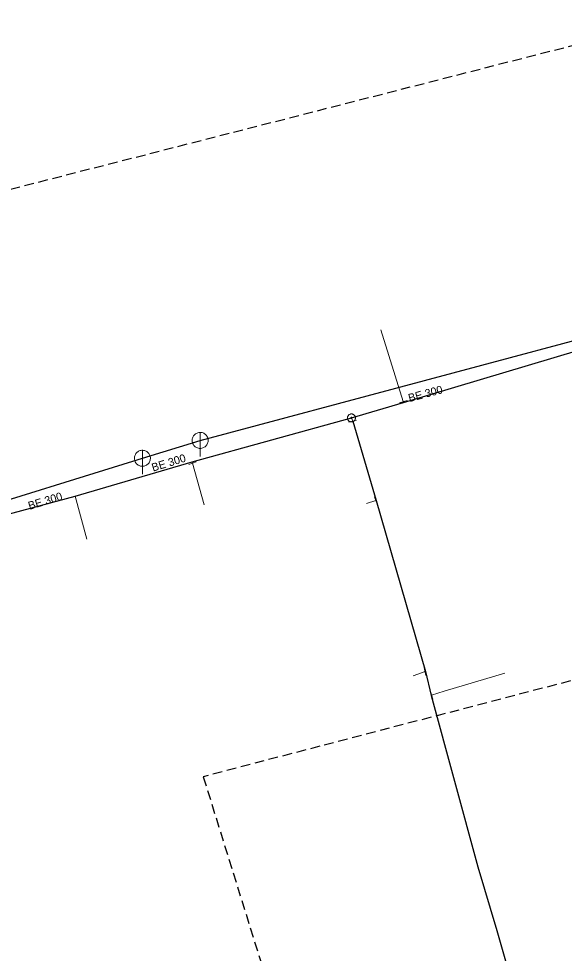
# Model space of a CAD drawing. Extents: x -690254 to -689100, y -975264 to -974703.
# Drawn here: x -689647.4 to -689579.1, y -974992.3 to -974875.5 of the extents above; entities that cross this region are included whole.
import ezdxf

# ---------------------------------------------------------------- set-up
doc = ezdxf.new("R2010")
doc.units = 0
doc.header["$LTSCALE"] = 0.4
doc.linetypes.add('MEDIUM_DASHED', pattern=[4.5, 3, -1.5])
for name, color, linetype, lineweight in [('1', 7, 'Continuous', 13), ('13', 7, 'Continuous', 13), ('14', 7, 'Continuous', 13), ('17', 7, 'Continuous', 25), ('22', 7, 'Continuous', 13), ('34', 7, 'Continuous', 13), ('47', 7, 'Continuous', 13), ('63', 7, 'MEDIUM_DASHED', 25)]:
    doc.layers.add(name, color=color, linetype=linetype, lineweight=lineweight)

msp = doc.modelspace()

# ---------------------------------------------------------------- linework, layer by layer
at = {"layer": '13'}
for p, q in [((-689599.281, -974923.341), (-689602.067, -974914.367)), ((-689625.632, -974931.027), (-689624.183, -974936.227)), ((-689640.32, -974935.166), (-689638.85, -974940.521)), ((-689602.706, -974935.695), (-689603.87, -974936.09)), ((-689596.556, -974957.073), (-689598.039, -974957.59))]:
    msp.add_line(p, q, dxfattribs=at)
msp.add_lwpolyline([(-689595.726, -974960.045), (-689594.17, -974959.52), (-689586.561, -974957.285)], dxfattribs=at)
at = {"layer": '14'}
for p, q in [((-689599.249, -974923.443), (-689599.281, -974923.341)), ((-689605.589, -974925.779), (-689605.756, -974925.377)), ((-689625.688, -974930.875), (-689625.632, -974931.027)), ((-689602.66, -974935.68), (-689602.706, -974935.695)), ((-689596.5, -974957.059), (-689596.556, -974957.073)), ((-689595.726, -974960.045), (-689595.8, -974960.07))]:
    msp.add_line(p, q, dxfattribs=at)
at = {"layer": '14', "lineweight": 25}
for points in [[(-689624.679, -974928.186), (-689568.576, -974913.204), (-689527.509, -974901.581), (-689488.181, -974889.533)], [(-689655.57, -974937.75), (-689631.897, -974930.421), (-689624.679, -974928.186)]]:
    msp.add_lwpolyline(points, dxfattribs=at)
at = {"layer": '17'}
for points in [[(-689605.756, -974925.377), (-689599.249, -974923.443), (-689573.976, -974915.931), (-689539.272, -974905.616), (-689481.914, -974888.101)], [(-689665.933, -974942.022), (-689640.32, -974935.166), (-689625.688, -974930.875), (-689605.756, -974925.377)], [(-689605.589, -974925.779), (-689602.66, -974935.68), (-689596.5, -974957.059), (-689595.8, -974960.07), (-689589.969, -974981.489), (-689587.59, -974989.42), (-689583.684, -975002.99), (-689581.596, -975011.39)]]:
    msp.add_lwpolyline(points, dxfattribs=at)
at = {"layer": '22'}
for p, q in [((-689624.679, -974930.186), (-689624.678, -974927.186)), ((-689631.897, -974932.421), (-689631.896, -974929.421))]:
    msp.add_line(p, q, dxfattribs=at)
for points in [[(-689623.679, -974928.186), (-689623.684, -974928.077), (-689623.702, -974927.969), (-689623.732, -974927.863), (-689623.772, -974927.762), (-689623.824, -974927.665), (-689623.886, -974927.575), (-689623.958, -974927.492), (-689624.038, -974927.418), (-689624.126, -974927.352), (-689624.22, -974927.297), (-689624.32, -974927.252), (-689624.425, -974927.219), (-689624.532, -974927.197), (-689624.641, -974927.187), (-689624.751, -974927.189), (-689624.859, -974927.203), (-689624.966, -974927.228), (-689625.069, -974927.265), (-689625.167, -974927.314), (-689625.259, -974927.372), (-689625.345, -974927.441), (-689625.422, -974927.518), (-689625.491, -974927.604), (-689625.55, -974927.696), (-689625.598, -974927.794), (-689625.635, -974927.897), (-689625.661, -974928.004), (-689625.675, -974928.112), (-689625.678, -974928.222), (-689625.668, -974928.331), (-689625.647, -974928.438), (-689625.613, -974928.542), (-689625.569, -974928.642), (-689625.514, -974928.737), (-689625.448, -974928.825), (-689625.374, -974928.905), (-689625.291, -974928.977), (-689625.201, -974929.039), (-689625.105, -974929.091), (-689625.003, -974929.132), (-689624.898, -974929.162), (-689624.79, -974929.18), (-689624.68, -974929.186), (-689624.571, -974929.18), (-689624.463, -974929.162), (-689624.358, -974929.133), (-689624.256, -974929.092), (-689624.159, -974929.04), (-689624.069, -974928.978), (-689623.986, -974928.907), (-689623.911, -974928.827), (-689623.846, -974928.739), (-689623.79, -974928.645), (-689623.746, -974928.545), (-689623.712, -974928.441), (-689623.69, -974928.333), (-689623.68, -974928.224)], [(-689630.897, -974930.421), (-689630.902, -974930.312), (-689630.92, -974930.204), (-689630.95, -974930.098), (-689630.99, -974929.997), (-689631.042, -974929.9), (-689631.104, -974929.81), (-689631.176, -974929.727), (-689631.256, -974929.653), (-689631.344, -974929.587), (-689631.438, -974929.532), (-689631.538, -974929.487), (-689631.643, -974929.454), (-689631.75, -974929.432), (-689631.859, -974929.422), (-689631.969, -974929.424), (-689632.077, -974929.438), (-689632.184, -974929.463), (-689632.287, -974929.5), (-689632.385, -974929.549), (-689632.477, -974929.607), (-689632.563, -974929.676), (-689632.64, -974929.753), (-689632.709, -974929.839), (-689632.768, -974929.931), (-689632.816, -974930.029), (-689632.853, -974930.132), (-689632.879, -974930.239), (-689632.893, -974930.347), (-689632.896, -974930.457), (-689632.886, -974930.566), (-689632.865, -974930.673), (-689632.831, -974930.777), (-689632.787, -974930.877), (-689632.732, -974930.972), (-689632.666, -974931.06), (-689632.592, -974931.14), (-689632.509, -974931.212), (-689632.419, -974931.274), (-689632.323, -974931.326), (-689632.221, -974931.367), (-689632.116, -974931.397), (-689632.008, -974931.415), (-689631.898, -974931.421), (-689631.789, -974931.415), (-689631.681, -974931.397), (-689631.576, -974931.368), (-689631.474, -974931.327), (-689631.377, -974931.275), (-689631.287, -974931.213), (-689631.204, -974931.142), (-689631.129, -974931.062), (-689631.064, -974930.974), (-689631.008, -974930.88), (-689630.964, -974930.78), (-689630.93, -974930.676), (-689630.908, -974930.568), (-689630.898, -974930.459)]]:
    msp.add_lwpolyline(points, close=True, dxfattribs=at)
at = {"layer": '34'}
for p, q in [((-689599.757, -974923.493), (-689598.804, -974923.189)), ((-689605.106, -974925.647), (-689606.071, -974925.909)), ((-689625.163, -974930.852), (-689626.1, -974931.2)), ((-689602.549, -974936.169), (-689602.861, -974935.219)), ((-689596.439, -974957.559), (-689596.671, -974956.586)), ((-689595.856, -974959.562), (-689595.596, -974960.527))]:
    msp.add_line(p, q, dxfattribs=at)
at = {"layer": '47'}
for points in [[(-689605.272, -974925.248), (-689605.289, -974925.198), (-689605.31, -974925.15), (-689605.336, -974925.105), (-689605.366, -974925.063), (-689605.402, -974925.023), (-689605.441, -974924.988), (-689605.483, -974924.958), (-689605.528, -974924.932), (-689605.576, -974924.91), (-689605.625, -974924.894), (-689605.677, -974924.883), (-689605.729, -974924.878), (-689605.781, -974924.877), (-689605.833, -974924.883), (-689605.884, -974924.893), (-689605.934, -974924.91), (-689605.982, -974924.931), (-689606.028, -974924.957), (-689606.069, -974924.987), (-689606.109, -974925.023), (-689606.144, -974925.062), (-689606.175, -974925.104), (-689606.201, -974925.15), (-689606.223, -974925.197), (-689606.238, -974925.246), (-689606.249, -974925.298), (-689606.255, -974925.35), (-689606.255, -974925.402), (-689606.249, -974925.454), (-689606.239, -974925.505), (-689606.222, -974925.555), (-689606.201, -974925.603), (-689606.176, -974925.649), (-689606.145, -974925.69), (-689606.109, -974925.73), (-689606.071, -974925.765), (-689606.029, -974925.796), (-689605.983, -974925.822), (-689605.935, -974925.844), (-689605.886, -974925.859), (-689605.834, -974925.87), (-689605.783, -974925.876), (-689605.73, -974925.876), (-689605.678, -974925.87), (-689605.627, -974925.86), (-689605.577, -974925.843), (-689605.529, -974925.822), (-689605.484, -974925.797), (-689605.442, -974925.766), (-689605.402, -974925.73), (-689605.367, -974925.692), (-689605.337, -974925.65), (-689605.311, -974925.605), (-689605.289, -974925.556), (-689605.273, -974925.507), (-689605.262, -974925.455), (-689605.257, -974925.404), (-689605.256, -974925.351), (-689605.262, -974925.299)], [(-689605.676, -974925.355), (-689605.679, -974925.347), (-689605.683, -974925.339), (-689605.687, -974925.332), (-689605.692, -974925.325), (-689605.697, -974925.319), (-689605.704, -974925.313), (-689605.711, -974925.308), (-689605.718, -974925.303), (-689605.726, -974925.3), (-689605.734, -974925.297), (-689605.743, -974925.296), (-689605.751, -974925.295), (-689605.76, -974925.295), (-689605.768, -974925.295), (-689605.777, -974925.297), (-689605.785, -974925.3), (-689605.793, -974925.304), (-689605.8, -974925.308), (-689605.807, -974925.313), (-689605.813, -974925.318), (-689605.819, -974925.325), (-689605.824, -974925.332), (-689605.829, -974925.339), (-689605.833, -974925.347), (-689605.835, -974925.355), (-689605.836, -974925.364), (-689605.837, -974925.372), (-689605.837, -974925.381), (-689605.837, -974925.389), (-689605.835, -974925.398), (-689605.832, -974925.406), (-689605.828, -974925.414), (-689605.824, -974925.421), (-689605.819, -974925.428), (-689605.814, -974925.434), (-689605.808, -974925.44), (-689605.8, -974925.445), (-689605.793, -974925.45), (-689605.785, -974925.454), (-689605.777, -974925.456), (-689605.768, -974925.457), (-689605.76, -974925.458), (-689605.751, -974925.458), (-689605.743, -974925.458), (-689605.734, -974925.456), (-689605.726, -974925.453), (-689605.718, -974925.449), (-689605.711, -974925.445), (-689605.704, -974925.44), (-689605.698, -974925.435), (-689605.692, -974925.429), (-689605.687, -974925.421), (-689605.682, -974925.414), (-689605.679, -974925.406), (-689605.676, -974925.398), (-689605.675, -974925.389), (-689605.674, -974925.381), (-689605.674, -974925.372), (-689605.674, -974925.364)]]:
    msp.add_lwpolyline(points, close=True, dxfattribs=at)
at = {"layer": '63'}
msp.add_lwpolyline([(-690175.832, -975238.167), (-690201.511, -975156.663), (-690201.511, -975156.663), (-689696.859, -975008.171), (-689696.859, -975008.171), (-689730.354, -974917.735), (-689730.354, -974917.735), (-689127.452, -974763.66), (-689127.452, -974763.66), (-689118.52, -974838.465), (-689118.52, -974838.465), (-689624.288, -974970.21), (-689624.288, -974970.21), (-689593.026, -975070.694), (-689593.026, -975070.694)], close=True, dxfattribs=at)

# ---------------------------------------------------------------- texts
at = {"layer": '1'}
for rotation, p in [(15, (-689598.5, -974923.397)), (17, (-689630.566, -974932.087)), (17, (-689646.011, -974936.868))]:
    msp.add_text('BE 300', height=1, rotation=rotation, dxfattribs=at).set_placement(p)

doc.saveas('drawing.dxf')
